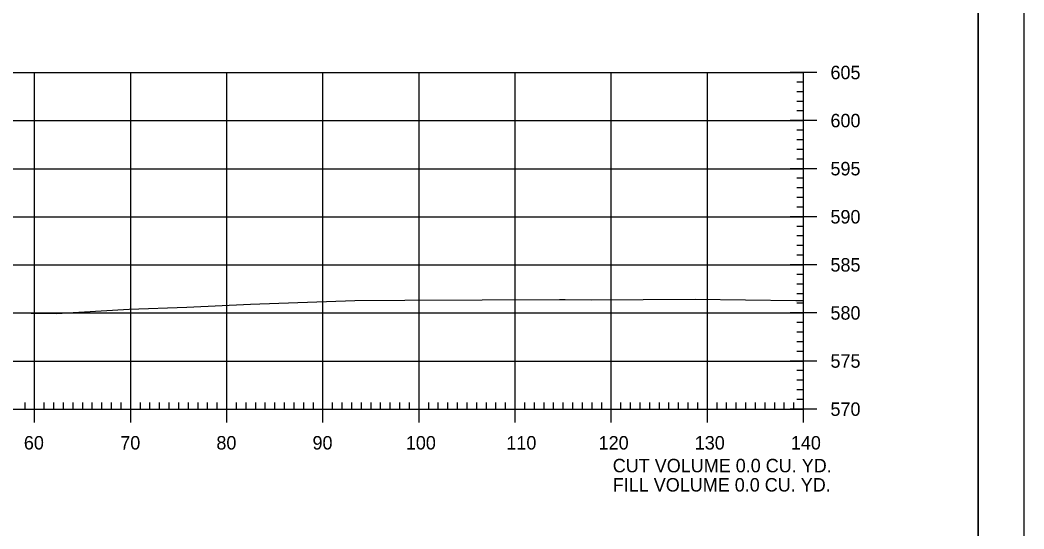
# Model space of a CAD drawing. Extents: x 961436 to 1372525, y 380079 to 2027791.
# Drawn here: x 1371253.4 to 1371357.8, y 380429.9 to 380482.8 of the extents above; entities that cross this region are included whole.
import ezdxf

# ---------------------------------------------------------------- set-up
doc = ezdxf.new("R2010")
doc.units = 0
for name, color, linetype in [('R_Axis', 7, 'Continuous'), ('R_Axis Annot', 7, 'Continuous'), ('R_Border', 7, 'Continuous'), ('R_Exist Surface', 7, 'Continuous'), ('R_Grid', 7, 'Continuous'), ('R_No Plot', 7, 'Continuous')]:
    doc.layers.add(name, color=color, linetype=linetype)

msp = doc.modelspace()

# ---------------------------------------------------------------- linework, layer by layer
at = {"layer": 'R_Axis'}
for p, q in [((1371336.28, 380477.4), (1371333.48, 380477.4)), ((1371334.88, 380442.4), (1371334.88, 380477.4)), ((1371334.88, 380476.4), (1371334.18, 380476.4)), ((1371334.88, 380475.4), (1371334.18, 380475.4)), ((1371334.88, 380474.4), (1371334.18, 380474.4)), ((1371334.88, 380473.4), (1371334.18, 380473.4)), ((1371336.28, 380472.4), (1371333.48, 380472.4)), ((1371334.88, 380471.4), (1371334.18, 380471.4)), ((1371334.88, 380470.4), (1371334.18, 380470.4)), ((1371334.88, 380469.4), (1371334.18, 380469.4)), ((1371334.88, 380468.4), (1371334.18, 380468.4)), ((1371336.28, 380467.4), (1371333.48, 380467.4)), ((1371334.88, 380466.4), (1371334.18, 380466.4)), ((1371334.88, 380465.4), (1371334.18, 380465.4)), ((1371334.88, 380464.4), (1371334.18, 380464.4)), ((1371334.88, 380463.4), (1371334.18, 380463.4)), ((1371336.28, 380462.4), (1371333.48, 380462.4)), ((1371334.88, 380461.4), (1371334.18, 380461.4)), ((1371334.88, 380460.4), (1371334.18, 380460.4)), ((1371334.88, 380459.4), (1371334.18, 380459.4)), ((1371334.88, 380458.4), (1371334.18, 380458.4)), ((1371336.28, 380457.4), (1371333.48, 380457.4)), ((1371334.88, 380456.4), (1371334.18, 380456.4)), ((1371334.88, 380455.4), (1371334.18, 380455.4)), ((1371334.88, 380454.4), (1371334.18, 380454.4)), ((1371334.88, 380453.4), (1371334.18, 380453.4)), ((1371336.28, 380452.4), (1371333.48, 380452.4)), ((1371334.88, 380451.4), (1371334.18, 380451.4)), ((1371334.88, 380450.4), (1371334.18, 380450.4)), ((1371334.88, 380449.4), (1371334.18, 380449.4)), ((1371334.88, 380448.4), (1371334.18, 380448.4)), ((1371336.28, 380447.4), (1371333.48, 380447.4)), ((1371334.88, 380446.4), (1371334.18, 380446.4)), ((1371334.88, 380445.4), (1371334.18, 380445.4)), ((1371334.88, 380444.4), (1371334.18, 380444.4)), ((1371253.88, 380442.4), (1371253.88, 380443.1)), ((1371254.88, 380441), (1371254.88, 380443.8)), ((1371255.88, 380442.4), (1371255.88, 380443.1)), ((1371256.88, 380442.4), (1371256.88, 380443.1)), ((1371257.88, 380442.4), (1371257.88, 380443.1)), ((1371258.88, 380442.4), (1371258.88, 380443.1)), ((1371259.88, 380442.4), (1371259.88, 380443.1)), ((1371260.88, 380442.4), (1371260.88, 380443.1)), ((1371261.88, 380442.4), (1371261.88, 380443.1)), ((1371262.88, 380442.4), (1371262.88, 380443.1)), ((1371263.88, 380442.4), (1371263.88, 380443.1)), ((1371264.88, 380441), (1371264.88, 380443.8)), ((1371265.88, 380442.4), (1371265.88, 380443.1)), ((1371266.88, 380442.4), (1371266.88, 380443.1)), ((1371267.88, 380442.4), (1371267.88, 380443.1)), ((1371268.88, 380442.4), (1371268.88, 380443.1)), ((1371269.88, 380442.4), (1371269.88, 380443.1)), ((1371270.88, 380442.4), (1371270.88, 380443.1)), ((1371271.88, 380442.4), (1371271.88, 380443.1)), ((1371272.88, 380442.4), (1371272.88, 380443.1)), ((1371273.88, 380442.4), (1371273.88, 380443.1)), ((1371274.88, 380441), (1371274.88, 380443.8)), ((1371275.88, 380442.4), (1371275.88, 380443.1)), ((1371276.88, 380442.4), (1371276.88, 380443.1)), ((1371277.88, 380442.4), (1371277.88, 380443.1)), ((1371278.88, 380442.4), (1371278.88, 380443.1)), ((1371279.88, 380442.4), (1371279.88, 380443.1)), ((1371280.88, 380442.4), (1371280.88, 380443.1)), ((1371281.88, 380442.4), (1371281.88, 380443.1)), ((1371282.88, 380442.4), (1371282.88, 380443.1)), ((1371283.88, 380442.4), (1371283.88, 380443.1)), ((1371284.88, 380441), (1371284.88, 380443.8)), ((1371285.88, 380442.4), (1371285.88, 380443.1)), ((1371286.88, 380442.4), (1371286.88, 380443.1)), ((1371287.88, 380442.4), (1371287.88, 380443.1)), ((1371288.88, 380442.4), (1371288.88, 380443.1)), ((1371289.88, 380442.4), (1371289.88, 380443.1)), ((1371290.88, 380442.4), (1371290.88, 380443.1)), ((1371291.88, 380442.4), (1371291.88, 380443.1)), ((1371292.88, 380442.4), (1371292.88, 380443.1)), ((1371293.88, 380442.4), (1371293.88, 380443.1)), ((1371294.88, 380441), (1371294.88, 380443.8)), ((1371295.88, 380442.4), (1371295.88, 380443.1)), ((1371296.88, 380442.4), (1371296.88, 380443.1)), ((1371297.88, 380442.4), (1371297.88, 380443.1)), ((1371298.88, 380442.4), (1371298.88, 380443.1)), ((1371299.88, 380442.4), (1371299.88, 380443.1)), ((1371300.88, 380442.4), (1371300.88, 380443.1)), ((1371301.88, 380442.4), (1371301.88, 380443.1)), ((1371302.88, 380442.4), (1371302.88, 380443.1)), ((1371303.88, 380442.4), (1371303.88, 380443.1)), ((1371304.88, 380441), (1371304.88, 380443.8)), ((1371305.88, 380442.4), (1371305.88, 380443.1)), ((1371306.88, 380442.4), (1371306.88, 380443.1)), ((1371307.88, 380442.4), (1371307.88, 380443.1)), ((1371308.88, 380442.4), (1371308.88, 380443.1)), ((1371309.88, 380442.4), (1371309.88, 380443.1)), ((1371310.88, 380442.4), (1371310.88, 380443.1)), ((1371311.88, 380442.4), (1371311.88, 380443.1)), ((1371312.88, 380442.4), (1371312.88, 380443.1)), ((1371313.88, 380442.4), (1371313.88, 380443.1)), ((1371314.88, 380441), (1371314.88, 380443.8)), ((1371315.88, 380442.4), (1371315.88, 380443.1)), ((1371316.88, 380442.4), (1371316.88, 380443.1)), ((1371317.88, 380442.4), (1371317.88, 380443.1)), ((1371318.88, 380442.4), (1371318.88, 380443.1)), ((1371319.88, 380442.4), (1371319.88, 380443.1)), ((1371320.88, 380442.4), (1371320.88, 380443.1)), ((1371321.88, 380442.4), (1371321.88, 380443.1)), ((1371322.88, 380442.4), (1371322.88, 380443.1)), ((1371323.88, 380442.4), (1371323.88, 380443.1)), ((1371324.88, 380441), (1371324.88, 380443.8)), ((1371325.88, 380442.4), (1371325.88, 380443.1)), ((1371326.88, 380442.4), (1371326.88, 380443.1)), ((1371327.88, 380442.4), (1371327.88, 380443.1)), ((1371328.88, 380442.4), (1371328.88, 380443.1)), ((1371329.88, 380442.4), (1371329.88, 380443.1)), ((1371330.88, 380442.4), (1371330.88, 380443.1)), ((1371331.88, 380442.4), (1371331.88, 380443.1)), ((1371332.88, 380442.4), (1371332.88, 380443.1)), ((1371333.88, 380442.4), (1371333.88, 380443.1)), ((1371334.88, 380443.4), (1371334.18, 380443.4)), ((1371334.88, 380441), (1371334.88, 380443.8)), ((1371054.88, 380442.4), (1371334.88, 380442.4)), ((1371336.28, 380442.4), (1371333.48, 380442.4))]:
    msp.add_line(p, q, dxfattribs=at)
at = {"layer": 'R_Border'}
msp.add_line((1371353.06, 380326.4), (1371353.06, 380531.86), dxfattribs=at)
at = {"layer": 'R_Exist Surface'}
msp.add_lwpolyline([(1371251.89, 380452.42), (1371257.16, 380452.35), (1371264.72, 380452.79), (1371270.72, 380452.99), (1371277.34, 380453.31), (1371288.19, 380453.71), (1371293.39, 380453.73), (1371309.48, 380453.79), (1371310.09, 380453.78), (1371312.79, 380453.76), (1371323.61, 380453.82), (1371334.07, 380453.71), (1371334.88, 380453.7)], dxfattribs=at)
at = {"layer": 'R_Grid'}
for p, q in [((1371054.88, 380477.4), (1371334.88, 380477.4)), ((1371254.88, 380442.4), (1371254.88, 380477.4)), ((1371264.88, 380442.4), (1371264.88, 380477.4)), ((1371274.88, 380442.4), (1371274.88, 380477.4)), ((1371284.88, 380442.4), (1371284.88, 380477.4)), ((1371294.88, 380442.4), (1371294.88, 380477.4)), ((1371304.88, 380442.4), (1371304.88, 380477.4)), ((1371314.88, 380442.4), (1371314.88, 380477.4)), ((1371324.88, 380442.4), (1371324.88, 380477.4)), ((1371334.88, 380442.4), (1371334.88, 380477.4)), ((1371054.88, 380472.4), (1371334.88, 380472.4)), ((1371054.88, 380467.4), (1371334.88, 380467.4)), ((1371054.88, 380462.4), (1371334.88, 380462.4)), ((1371054.88, 380457.4), (1371334.88, 380457.4)), ((1371054.88, 380452.4), (1371334.88, 380452.4)), ((1371054.88, 380447.4), (1371334.88, 380447.4)), ((1371054.88, 380442.4), (1371334.88, 380442.4))]:
    msp.add_line(p, q, dxfattribs=at)
at = {"layer": 'R_No Plot'}
for points in [[(1371024.47, 380535.75), (1371357.81, 380535.75), (1371357.81, 380322.41), (1371024.47, 380322.41)], [(1371270.8, 380531.86), (1371290.42, 380531.86), (1371290.42, 380521.98), (1371306.53, 380521.98), (1371329.73, 380521.98), (1371329.85, 380493.82), (1371353.06, 380493.82), (1371353.06, 380326.4), (1371036.88, 380326.4), (1371036.88, 380531.86)]]:
    msp.add_lwpolyline(points, close=True, dxfattribs=at)

# ---------------------------------------------------------------- texts
at = {"layer": 'R_Axis Annot'}
for s, p in [('605', (1371337.68, 380476.7)), ('600', (1371337.68, 380471.7)), ('595', (1371337.68, 380466.7)), ('590', (1371337.68, 380461.7)), ('585', (1371337.68, 380456.7)), ('580', (1371337.68, 380451.7)), ('575', (1371337.68, 380446.7)), ('570', (1371337.68, 380441.7)), ('60', (1371253.76, 380438.2)), ('70', (1371263.79, 380438.2)), ('80', (1371273.79, 380438.2)), ('90', (1371283.79, 380438.2)), ('100', (1371293.5, 380438.2)), ('110', (1371303.96, 380438.2)), ('120', (1371313.56, 380438.2)), ('130', (1371323.56, 380438.2)), ('140', (1371333.56, 380438.2)), ('CUT VOLUME 0.0 CU. YD.', (1371315.03, 380435.83)), ('FILL VOLUME 0.0 CU. YD.', (1371315.03, 380433.83))]:
    msp.add_text(s, height=1.4, dxfattribs=at).set_placement(p)

doc.saveas('drawing.dxf')
